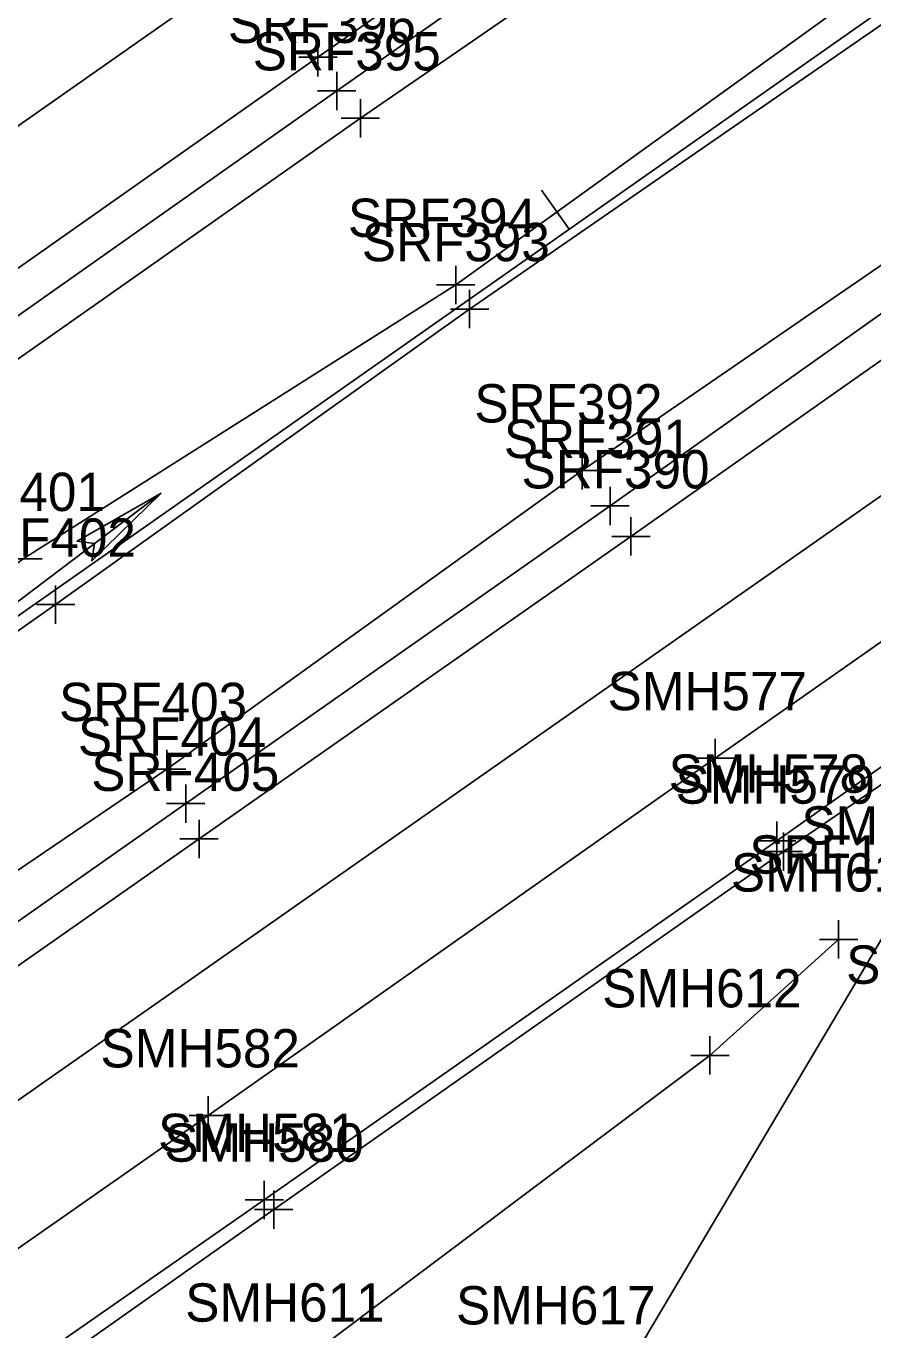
# Model space of a CAD drawing. Extents: x 941041 to 969446, y 397014 to 416764.
# Drawn here: x 952192.2 to 952280.5, y 403399.5 to 403535.6 of the extents above; entities that cross this region are included whole.
import ezdxf

# ---------------------------------------------------------------- set-up
doc = ezdxf.new("R2010")
doc.units = 0
for name, color, linetype in [('SURVEY - CENTERLINE - Preliminary', 7, 'Continuous'), ('SURVEY - CENTERLINE - Preliminary Curve Text', 7, 'Continuous'), ('SURVEY - DRAINAGE - Area Shapes', 7, 'Continuous'), ('SURVEY - DRAINAGE - Area Shapes Text', 7, 'Continuous'), ('SURVEY - DRAINAGE - Pipes and Culverts - Points - Numbers', 7, 'Continuous'), ('SURVEY - DTM - Breaklines', 7, 'Continuous'), ('SURVEY - DTM - Breaklines - Points - Locators', 7, 'Continuous'), ('SURVEY - DTM - Breaklines - Points - Numbers', 7, 'Continuous'), ('SURVEY - DTM - Spot Points - Point Numbers', 7, 'Continuous'), ('SURVEY - TRANSPORTATION - Features', 7, 'Continuous'), ('SURVEY - TRANSPORTATION - Features - Points - Locators', 7, 'Continuous'), ('SURVEY - TRANSPORTATION - Features - Points - Numbers', 7, 'Continuous'), ('SURVEY - TRANSPORTATION - Roads', 7, 'Continuous'), ('SURVEY - TRANSPORTATION - Roads - Points - Locators', 7, 'Continuous'), ('SURVEY - TRANSPORTATION - Roads - Points - Numbers', 7, 'Continuous')]:
    doc.layers.add(name, color=color, linetype=linetype)

msp = doc.modelspace()

# ---------------------------------------------------------------- linework, layer by layer
at = {"layer": 'SURVEY - CENTERLINE - Preliminary'}
msp.add_line((950966.25, 402614.81), (953884.31, 404661.52), dxfattribs=at)
msp.add_line((950966.25, 402614.81), (953884.31, 404661.52), dxfattribs=at)
msp.add_line((950966.25, 402614.81), (953884.31, 404661.52), dxfattribs=at)
at = {"layer": 'SURVEY - CENTERLINE - Preliminary Curve Text'}
msp.add_line((952248.84, 403514.41), (952245.97, 403518.5), dxfattribs=at)
at = {"layer": 'SURVEY - DRAINAGE - Area Shapes'}
for points in [[(951145.6, 402792.15), (951562.19, 403084.02), (952475.83, 403724.71), (952754.77, 403922.8), (952578.99, 403846.21), (952455.44, 403792), (952334.19, 403750.29), (951972.51, 403632.53), (951887.41, 403584.59)], [(950765.73, 402528.11), (950855.07, 402487.28), (951056.09, 402625.14), (951609.08, 403015.7), (952524.78, 403657.05), (952475.83, 403724.71)]]:
    msp.add_lwpolyline(points, dxfattribs=at)
at = {"layer": 'SURVEY - DRAINAGE - Area Shapes Text'}
msp.add_line((952206.28, 403486.88), (952176.37, 403464.24), dxfattribs=at)
msp.add_lwpolyline([(952206.28, 403486.88), (952199.02, 403479.82), (952199.31, 403481.6), (952197.49, 403481.85)], close=True, dxfattribs=at)
msp.add_lwpolyline([(952206.28, 403486.88), (952199.02, 403479.82), (952199.31, 403481.6), (952197.49, 403481.85), (952206.28, 403486.88)], dxfattribs=at)
at = {"layer": 'SURVEY - DTM - Breaklines'}
for points in [[(952483.82, 403681.92), (952427.27, 403642.38), (952380.72, 403610.67), (952332.46, 403575.38), (952287.62, 403545.12), (952237.01, 403508.6), (952191.86, 403480), (952144.06, 403444.49), (952098.2, 403411.83), (952049.8, 403377.02), (952005.42, 403346.02), (951961.72, 403316.38), (951908.1, 403283.08), (951836.08, 403227.91)], [(952485.25, 403679.95), (952429.13, 403639.43), (952382.71, 403607.61), (952334.17, 403572.43), (952289.83, 403541.57), (952238.45, 403506.07), (952195.26, 403475.23), (952146.22, 403440.76), (952099.32, 403409.75), (952050.92, 403375.53), (952007.43, 403342.26), (951963.47, 403311.23), (951910.97, 403277.41), (951839.65, 403222.38)], [(952284.32, 403445.19), (952160.86, 403236.96), (952125.87, 403192.45), (952077.94, 403136.62), (952039.19, 403098.25), (952006.25, 403068.24), (951969.46, 403038.09), (951934.26, 403008.18), (951912.19, 402997.34), (951900.8, 403002.03), (951909.31, 403040.46), (951919.74, 403082.57), (951927.08, 403105.04), (951926.24, 403141.28), (951910.03, 403171.31), (951930.4, 403184.14)], [(951846.56, 403146.1), (951882.59, 403170.26), (951887.03, 403170.6), (951935.22, 403196.94), (951981.81, 403226.14), (952031.67, 403259.48), (952078.26, 403295.42), (952132.19, 403332.31), (952180.72, 403366.29), (952219.86, 403395.41), (952263.53, 403428.2), (952276.96, 403440.29)]]:
    msp.add_lwpolyline(points, dxfattribs=at)
at = {"layer": 'SURVEY - DTM - Breaklines - Points - Locators'}
for p, q in [((952237.01, 403510.6), (952237.01, 403506.6)), ((952239.01, 403508.6), (952235.01, 403508.6)), ((952238.45, 403508.07), (952238.45, 403504.07)), ((952240.45, 403506.07), (952236.45, 403506.07)), ((952193.86, 403480), (952189.86, 403480)), ((952195.26, 403477.23), (952195.26, 403473.23)), ((952197.26, 403475.23), (952193.26, 403475.23)), ((952276.96, 403442.29), (952276.96, 403438.29)), ((952278.96, 403440.29), (952274.96, 403440.29)), ((952263.53, 403430.2), (952263.53, 403426.2)), ((952265.53, 403428.2), (952261.53, 403428.2))]:
    msp.add_line(p, q, dxfattribs=at)
at = {"layer": 'SURVEY - TRANSPORTATION - Features'}
for points in [[(952645.64, 403820.24), (952597.37, 403785.52), (952553.07, 403755.16), (952508.33, 403722.84), (952461.02, 403689.31), (952413.89, 403656.85), (952372.14, 403627.74), (952321.41, 403592.67), (952277.52, 403560.71), (952227.07, 403525.98), (952181.35, 403493.84), (952134.56, 403460.33), (952087.52, 403428.37), (952039.89, 403391.89), (951995.48, 403362.71), (951950.18, 403331.94), (951900.76, 403296.02), (951846.55, 403258.26)], [(952622.56, 403749.53), (952577.8, 403717.92), (952532.08, 403686.84), (952486.03, 403653.05), (952440.27, 403622.51), (952394.74, 403590.13), (952344.15, 403555.61), (952299.81, 403523.27), (952250.2, 403489.24), (952206.86, 403458.08), (952156.3, 403423.75), (952110.49, 403390.56), (952062.35, 403358.41), (952017.69, 403325.18), (951971.92, 403293.52), (951916.96, 403254.99), (951879.97, 403228.71), (951856.72, 403212.68)], [(952356.31, 403508.85), (952319.54, 403482.53), (952271.2, 403449.46), (952218.02, 403412.1), (952168.51, 403377.19), (952118.64, 403342.5), (952070.41, 403308.53), (952018.6, 403272.33), (951969.85, 403238.11), (951920.07, 403203.33), (951882.16, 403176.11), (951845.47, 403150.79)]]:
    msp.add_lwpolyline(points, dxfattribs=at)
at = {"layer": 'SURVEY - TRANSPORTATION - Features - Points - Locators'}
for p, q in [((952227.07, 403527.98), (952227.07, 403523.98)), ((952229.07, 403525.98), (952225.07, 403525.98)), ((952250.2, 403491.24), (952250.2, 403487.24)), ((952252.2, 403489.24), (952248.2, 403489.24)), ((952206.86, 403460.08), (952206.86, 403456.08)), ((952208.86, 403458.08), (952204.86, 403458.08)), ((952271.2, 403451.46), (952271.2, 403447.46)), ((952273.2, 403449.46), (952269.2, 403449.46)), ((952218.02, 403414.1), (952218.02, 403410.1)), ((952220.02, 403412.1), (952216.02, 403412.1))]:
    msp.add_line(p, q, dxfattribs=at)
at = {"layer": 'SURVEY - TRANSPORTATION - Roads'}
for points in [[(952641.53, 403826.17), (952594.17, 403793.02), (952548.96, 403761.1), (952503.9, 403729.55), (952456.48, 403696.45), (952409.67, 403663.54), (952367.99, 403634.29), (952317.16, 403598.59), (952272.62, 403567.27), (952222.63, 403532.35), (952176.87, 403500.19), (952130.48, 403467.59), (952084.27, 403435.24), (952034.3, 403400.18), (951990.77, 403369.82), (951946.58, 403338.79), (951896.13, 403303.32), (951845.2, 403267.54)], [(952643.61, 403822.77), (952594.67, 403788.44), (952551.07, 403757.87), (952505.87, 403726.23), (952458.48, 403693.09), (952411.72, 403660.12), (952370.22, 403630.98), (952318.83, 403594.87), (952274.8, 403564.01), (952224.59, 403528.84), (952179.21, 403496.84), (952131.71, 403463.73), (952086.34, 403432.04), (952035.93, 403396.55), (951992.92, 403366.55), (951948.08, 403335.21), (951898.42, 403300.16), (951843.97, 403261.96)], [(952625.22, 403746.95), (952579.91, 403715.1), (952534.83, 403683.49), (952487.43, 403650.41), (952442.83, 403619.09), (952396.91, 403586.46), (952346.61, 403551.28), (952301.65, 403519.95), (952253.11, 403485.53), (952208.83, 403454.47), (952159.44, 403419.8), (952112.68, 403387.11), (952066.16, 403354.45), (952019.33, 403321.73), (951973.66, 403289.75), (951918.65, 403251.32), (951882.81, 403225.68), (951856.94, 403208.02)], [(952627.47, 403743.75), (952581.75, 403711.66), (952537.07, 403680.23), (952488.75, 403646.32), (952445.47, 403615.87), (952397.1, 403581.89), (952349.33, 403548.4), (952302.96, 403515.9), (952255.29, 403482.36), (952210.22, 403450.79), (952161.93, 403416.95), (952113.95, 403383.26), (952068.49, 403351.38), (952021.19, 403318.27), (951975.59, 403286.18), (951920.11, 403247.28), (951884.29, 403222.24), (951858.06, 403203.77)], [(952447.34, 403587.64), (952403.74, 403556.93), (952357.95, 403524.8), (952311.77, 403492.65), (952264.09, 403459.22), (952211.18, 403421.94), (952159.19, 403385.58), (952111.45, 403351.91), (952063.96, 403319.03), (952011.56, 403282.13), (951962.38, 403247.78), (951912.18, 403212.48), (951876.49, 403187.38), (951846.26, 403165.91)], [(952363.66, 403516.11), (952318.6, 403484.64), (952270.5, 403450.6), (952217.03, 403413.11), (952165.82, 403377.48), (952117.66, 403343.68), (952069.64, 403309.92), (952017.59, 403273.34), (951968.61, 403239.23), (951919.39, 403204.95), (951881.03, 403178.29), (951848.45, 403157.23)]]:
    msp.add_lwpolyline(points, dxfattribs=at)
at = {"layer": 'SURVEY - TRANSPORTATION - Roads - Points - Locators'}
for p, q in [((952222.63, 403534.35), (952222.63, 403530.35)), ((952224.63, 403532.35), (952220.63, 403532.35)), ((952224.59, 403530.84), (952224.59, 403526.84)), ((952226.59, 403528.84), (952222.59, 403528.84)), ((952253.11, 403487.53), (952253.11, 403483.53)), ((952255.11, 403485.53), (952251.11, 403485.53)), ((952255.29, 403484.36), (952255.29, 403480.36)), ((952257.29, 403482.36), (952253.29, 403482.36)), ((952264.09, 403461.22), (952264.09, 403457.22)), ((952266.09, 403459.22), (952262.09, 403459.22)), ((952208.83, 403456.47), (952208.83, 403452.47)), ((952210.83, 403454.47), (952206.83, 403454.47)), ((952210.22, 403452.79), (952210.22, 403448.79)), ((952270.5, 403452.6), (952270.5, 403448.6)), ((952212.22, 403450.79), (952208.22, 403450.79)), ((952272.5, 403450.6), (952268.5, 403450.6)), ((952211.18, 403423.94), (952211.18, 403419.94)), ((952213.18, 403421.94), (952209.18, 403421.94)), ((952217.03, 403415.11), (952217.03, 403411.11)), ((952219.03, 403413.11), (952215.03, 403413.11))]:
    msp.add_line(p, q, dxfattribs=at)

# ---------------------------------------------------------------- texts
at = {"layer": 'SURVEY - DRAINAGE - Pipes and Culverts - Points - Numbers'}
msp.add_text('SRF1743', height=4, dxfattribs=at).set_placement((952267.64, 403447.16))
at = {"layer": 'SURVEY - DTM - Breaklines - Points - Numbers'}
for s, p in [('SRF394', (952225.77, 403513.6)), ('SRF393', (952227.21, 403511.07)), ('SRF401', (952180.78, 403485)), ('SRF402', (952184.02, 403480.23)), ('SMH614', (952273.08, 403450.19)), ('SMH613', (952265.72, 403445.29)), ('SMH612', (952252.29, 403433.2)), ('SMH611', (952208.78, 403400.41))]:
    msp.add_text(s, height=4, dxfattribs=at).set_placement(p)
at = {"layer": 'SURVEY - DTM - Spot Points - Point Numbers'}
for s, p in [('SMH616', (952277.75, 403435.67)), ('SMH617', (952237.04, 403400.12))]:
    msp.add_text(s, height=4, dxfattribs=at).set_placement(p)
at = {"layer": 'SURVEY - TRANSPORTATION - Features - Points - Numbers'}
for s, p in [('SRF395', (952215.83, 403530.98)), ('SRF392', (952238.96, 403494.24)), ('SRF403', (952195.62, 403463.08)), ('SMH579', (952259.94, 403454.46)), ('SMH580', (952206.6, 403417.1))]:
    msp.add_text(s, height=4, dxfattribs=at).set_placement(p)
at = {"layer": 'SURVEY - TRANSPORTATION - Roads - Points - Numbers'}
for s, p in [('SRF396', (952213.24, 403533.84)), ('SRF391', (952242.03, 403490.53)), ('SRF390', (952243.87, 403487.36)), ('SMH577', (952252.85, 403464.22)), ('SRF404', (952197.59, 403459.47)), ('SRF405', (952198.98, 403455.79)), ('SMH578', (952259.22, 403455.6)), ('SMH582', (952199.94, 403426.94)), ('SMH581', (952205.95, 403418.11))]:
    msp.add_text(s, height=4, dxfattribs=at).set_placement(p)

doc.saveas('drawing.dxf')
